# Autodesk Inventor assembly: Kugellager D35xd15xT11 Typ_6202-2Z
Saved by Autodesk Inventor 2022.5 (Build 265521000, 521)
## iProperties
Created: 2024-12
Part Number: Kugellager D35xd15xT11 Typ_6202-2Z
Document SubType Name: Assembly
Designer: AdminForWorker
Title: Kugellager D35xd15xT11 Typ_6202-2Z v1
Author: AdminForWorker
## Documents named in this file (5)
- c:\worker\convert-fusion-r05-cosv3\tmp\job-1\111\temp\files\18f9c586-b0fd-4ec9-83df-4c1c4486ead0\5a6233e7-9700-4054-a5d5-f6b09664a90e.zip.iam
- c:\worker\convert-fusion-r05-cosv3\tmp\job-1\111\temp\files\18f9c586-b0fd-4ec9-83df-4c1c4486ead0\6202-2Z_InnerRing.ipt
- c:\worker\convert-fusion-r05-cosv3\tmp\job-1\111\temp\files\18f9c586-b0fd-4ec9-83df-4c1c4486ead0\6202-2Z_Ball.ipt
- c:\worker\convert-fusion-r05-cosv3\tmp\job-1\111\temp\files\18f9c586-b0fd-4ec9-83df-4c1c4486ead0\6202-2Z_OuterRing.ipt
- c:\worker\convert-fusion-r05-cosv3\tmp\job-1\111\temp\files\18f9c586-b0fd-4ec9-83df-4c1c4486ead0\6202-2Z_Shield.ipt
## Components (23 placed, 4 different names)
1. 6202-2Z_InnerRing:1
2. 6202-2Z_Ball:1
3. 6202-2Z_InnerRing:2
4. 6202-2Z_InnerRing:3
5. 6202-2Z_InnerRing:4
6. 6202-2Z_InnerRing:5
7. 6202-2Z_InnerRing:6
8. 6202-2Z_InnerRing:7
9. 6202-2Z_InnerRing:8
10. 6202-2Z_InnerRing:9
11. 6202-2Z_InnerRing:10
12. 6202-2Z_Ball:2
13. 6202-2Z_Ball:3
14. 6202-2Z_Ball:4
15. 6202-2Z_Ball:5
16. 6202-2Z_Ball:6
17. 6202-2Z_Ball:7
18. 6202-2Z_Ball:8
19. 6202-2Z_Ball:9
20. 6202-2Z_Ball:10
21. 6202-2Z_OuterRing:1
22. 6202-2Z_Shield:1
23. 6202-2Z_Shield:2
